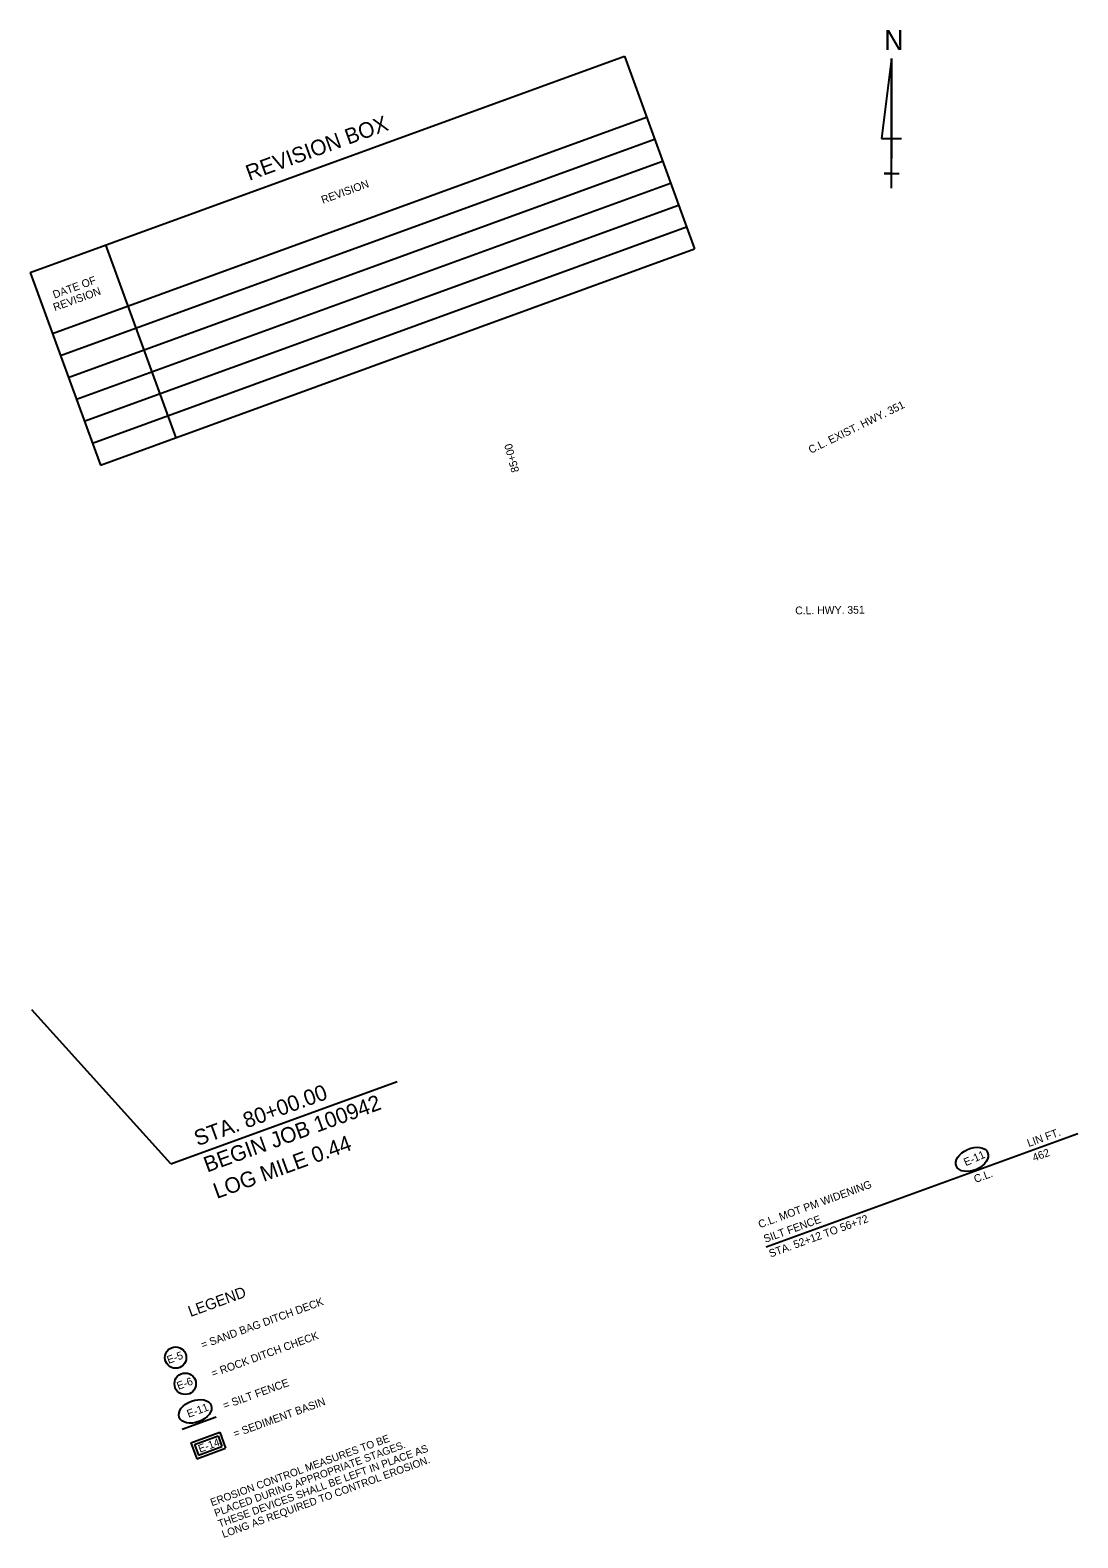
# Model space of a CAD drawing. Extents: x 1710835 to 1712392, y 548501 to 549912.
# Drawn here: x 1710835 to 1711642, y 548501 to 549662 of the extents above; entities that cross this region are included whole.
import ezdxf

# ---------------------------------------------------------------- set-up
doc = ezdxf.new("R2010")
doc.units = 0
for name, color, linetype in [('R_Horz Alg', 7, 'Continuous'), ('R_Horz Alg Annot', 7, 'Continuous'), ('R_MOT', 7, 'Continuous'), ('R_Proposed Const Limits_Fill', 7, 'Continuous')]:
    doc.layers.add(name, color=color, linetype=linetype)

msp = doc.modelspace()

# ---------------------------------------------------------------- linework, layer by layer
at = {"layer": 'R_Horz Alg'}
for p, q in [((1711498.4, 549640), (1711490.7, 549578.4)), ((1711498.4, 549540), (1711498.4, 549640)), ((1711498.4, 549640), (1711498.4, 549563)), ((1711490.7, 549578.4), (1711506.1, 549578.4)), ((1711498.4, 549540), (1711498.4, 549563)), ((1711498.4, 549551.5), (1711492.7, 549551.5)), ((1711492.7, 549551.5), (1711504.2, 549551.5)), ((1711498.4, 549540), (1711498.4, 549551.5))]:
    msp.add_line(p, q, dxfattribs=at)
at = {"layer": 'R_Horz Alg Annot'}
for p, q in [((1710835.2, 549475.2), (1711292.7, 549641.7)), ((1711292.7, 549641.7), (1711346.7, 549493.3)), ((1710852.3, 549428.2), (1711309.8, 549594.7)), ((1710858.5, 549411.3), (1711315.9, 549577.8)), ((1710864.6, 549394.4), (1711322.1, 549560.9)), ((1710870.8, 549377.5), (1711328.2, 549544)), ((1710876.9, 549360.6), (1711334.4, 549527.1)), ((1710883.1, 549343.7), (1711340.5, 549510.2)), ((1710889.3, 549326.8), (1711346.7, 549493.3)), ((1710893.3, 549496.4), (1710947.3, 549347.9)), ((1710835.2, 549475.2), (1710889.3, 549326.8)), ((1710943.6, 548788.9), (1711117.8, 548852.3)), ((1711402, 548724.8), (1711641.9, 548812.1))]:
    msp.add_line(p, q, dxfattribs=at)
msp.add_lwpolyline([(1710943.6, 548788.9), (1710836.5, 548907.3)], dxfattribs=at)
at = {"layer": 'R_Proposed Const Limits_Fill'}
for p, q in [((1710959, 548574), (1710981.2, 548582.1)), ((1710981.2, 548582.1), (1710985.7, 548569.8)), ((1710959, 548574), (1710963.5, 548561.7)), ((1710961.8, 548572.7), (1710979.9, 548579.3)), ((1710961.8, 548572.7), (1710964.8, 548564.5)), ((1710963.5, 548561.7), (1710985.7, 548569.8)), ((1710964.8, 548564.5), (1710982.9, 548571.1)), ((1710979.9, 548579.3), (1710982.9, 548571.1))]:
    msp.add_line(p, q, dxfattribs=at)
msp.add_lwpolyline([(1710952.2, 548584.6), (1710978.4, 548594.1)], dxfattribs=at)
for centre in [(1710947.2, 548639.6), (1710954.6, 548619.4)]:
    msp.add_circle(centre, 8.26, dxfattribs=at)
for centre, major_axis in [((1711560.4, 548792.2), (12, 5.3)), ((1710962.3, 548598.2), (12.3, 4.5))]:
    msp.add_ellipse(centre, major_axis=major_axis, ratio=0.638788, dxfattribs=at)

# ---------------------------------------------------------------- texts
at = {"layer": 'R_Horz Alg'}
msp.add_text('N', height=15.4, dxfattribs=at).set_placement((1711492.8, 549646.4))
at = {"layer": 'R_Horz Alg Annot'}
for s, height, rotation, p in [('REVISION BOX', 12, 20, (1711003.9, 549545.7)), ('REVISION', 6, 20, (1711060.6, 549528)), ('DATE OF', 6, 20, (1710853.9, 549455)), ('REVISION', 6, 20, (1710854.2, 549445.3)), ('C.L. EXIST. HWY. 351', 6, 26.1667, (1711436.3, 549335.5)), ('C.L. HWY. 351', 6, 0.6428, (1711424.3, 549211.9)), ('STA. 80+00.00', 12, 20, (1710964.1, 548802.3)), ('BEGIN JOB 100942', 12, 20, (1710971.5, 548782)), ('LIN FT.', 6, 20, (1711604.1, 548801.7)), ('LOG MILE 0.44', 12, 20, (1710978.9, 548761.7)), ('462', 6, 20, (1711608.2, 548790.5)), ('C.L.', 6, 20, (1711563.1, 548774)), ('C.L. MOT PM WIDENING', 6, 20, (1711397.1, 548739.1)), ('SILT FENCE', 6, 20, (1711401.2, 548727.9)), ('STA. 52+12 TO 56+72', 6, 20, (1711405.3, 548716.6))]:
    msp.add_text(s, height=height, rotation=rotation, dxfattribs=at).set_placement(p)
at = {"layer": 'R_MOT'}
msp.add_text('85+00', height=6, rotation=104.9919, dxfattribs=at).set_placement((1711211.8, 549322.1))
at = {"layer": 'R_Proposed Const Limits_Fill'}
for s, height, rotation, p in [('E-11', 6, 23.8359, (1711555.6, 548786.9)), ('LEGEND', 8.44, 20, (1710958.7, 548670.8)), ('= SAND BAG DITCH DECK', 6, 20, (1710968, 548646.3)), ('= ROCK DITCH CHECK', 6, 20, (1710976, 548624.4)), ('E-5 ', 6, 20, (1710941.8, 548634.7)), ('E-6 ', 6, 20.4005, (1710949.4, 548614.7)), ('= SILT FENCE', 6, 20, (1710985, 548599.7)), ('E-11', 6, 20.2144, (1710957.2, 548593.2)), ('= SEDIMENT BASIN', 6, 20, (1710992.9, 548577.9)), ('E-14', 6, 19.9884, (1710965.9, 548566.3)), ('EROSION CONTROL MEASURES TO BE', 5.769, 20, (1710975.2, 548525.1)), ('PLACED DURING APPROPRIATE STAGES. ', 5.769, 20, (1710978.2, 548516.9)), ('THESE DEVICES SHALL BE LEFT IN PLACE AS ', 5.769, 20, (1710981.1, 548508.7)), ('LONG AS REQUIRED TO CONTROL EROSION.', 5.769, 20, (1710984.1, 548500.6))]:
    msp.add_text(s, height=height, rotation=rotation, dxfattribs=at).set_placement(p)

doc.saveas('drawing.dxf')
